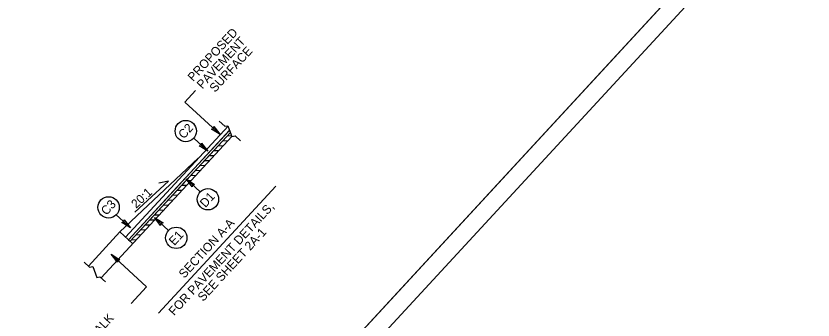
# Model space of a CAD drawing. Extents: x 1768274 to 1769121, y 999922 to 1000687.
# Drawn here: x 1768915.3 to 1769121.4, y 1000054.9 to 1000133.4 of the extents above; entities that cross this region are included whole.
import ezdxf

# ---------------------------------------------------------------- set-up
doc = ezdxf.new("R2010")
doc.units = 0
for name, color, linetype in [('E_NCDOT_Terrain_Model_Contour_Imported', 7, 'Continuous'), ('E_NCDOT_Terrain_Model_Contour_Major', 7, 'Continuous'), ('E_NCDOT_Terrain_Model_Contour_Minor', 7, 'Continuous'), ('E_NCDOT_Terrain_Model_Spot_Elevation', 7, 'Continuous'), ('E_NCDOT_Terrain_Model_Triangles', 7, 'Continuous')]:
    doc.layers.add(name, color=color, linetype=linetype)

msp = doc.modelspace()

# ---------------------------------------------------------------- linework, layer by layer
at = {"layer": 'E_NCDOT_Terrain_Model_Contour_Imported'}
msp.add_lwpolyline([(1768737.29, 1000073.61), (1768947.71, 1000301.25), (1769102.65, 1000158.03), (1768892.23, 999930.38)], close=True, dxfattribs=at)
at = {"layer": 'E_NCDOT_Terrain_Model_Contour_Major'}
msp.add_line((1768892.23, 999930.38), (1769116.23, 1000172.72), dxfattribs=at)
at = {"layer": 'E_NCDOT_Terrain_Model_Contour_Minor'}
msp.add_lwpolyline([(1768944.76, 1000075.2), (1768957.91, 1000089.43), (1768970.71, 1000103.28), (1768970.49, 1000103.9), (1768970.28, 1000103.68), (1768956.94, 1000089.24), (1768944.33, 1000075.6)], close=True, dxfattribs=at)
at = {"layer": 'E_NCDOT_Terrain_Model_Spot_Elevation'}
msp.add_lwpolyline([(1768729.03, 1000071.31), (1768959.82, 1000320.98), (1769121.37, 1000171.65), (1768890.59, 999921.97)], close=True, dxfattribs=at)
at = {"layer": 'E_NCDOT_Terrain_Model_Triangles'}
for p, q in [((1768958.95, 1000111.17), (1768961.7, 1000114.15)), ((1768968.06, 1000102.74), (1768958.95, 1000111.17)), ((1768967.83, 1000106.2), (1768969.24, 1000104.89)), ((1768970.11, 1000104.96), (1768943.6, 1000076.28)), ((1768970.49, 1000103.9), (1768944.33, 1000075.6)), ((1768969.24, 1000104.89), (1768970.08, 1000105.06)), ((1768970.08, 1000105.06), (1768971.08, 1000102.25)), ((1768971.07, 1000102.27), (1768937.31, 1000065.74)), ((1768970.71, 1000103.28), (1768944.76, 1000075.2)), ((1768964.87, 1000098.44), (1768961.22, 1000101.81)), ((1768971.03, 1000102.4), (1768969.86, 1000102.35)), ((1768971.08, 1000102.25), (1768971.92, 1000102.41)), ((1768971.92, 1000102.41), (1768973.33, 1000101.11)), ((1768968.84, 1000099.85), (1768967.5, 1000099.8)), ((1768970.02, 1000101.13), (1768968.68, 1000101.08)), ((1768967.66, 1000098.57), (1768966.32, 1000098.52)), ((1768962.41, 1000096.64), (1768942.16, 1000077.61)), ((1768965.3, 1000096.02), (1768963.96, 1000095.97)), ((1768966.48, 1000097.3), (1768965.14, 1000097.24)), ((1768962.93, 1000093.46), (1768961.6, 1000093.41)), ((1768964.12, 1000094.74), (1768962.78, 1000094.69)), ((1768959.23, 1000091.33), (1768962.87, 1000087.96)), ((1768961.75, 1000092.19), (1768960.42, 1000092.13)), ((1768954.72, 1000090.77), (1768946.02, 1000082.74)), ((1768952.13, 1000056.63), (1768982.44, 1000089.42)), ((1768954.72, 1000090.77), (1768952.18, 1000090.19)), ((1768959.39, 1000089.63), (1768958.05, 1000089.58)), ((1768960.57, 1000090.91), (1768959.24, 1000090.86)), ((1768958.21, 1000088.35), (1768956.87, 1000088.3)), ((1768955.85, 1000085.8), (1768954.51, 1000085.75)), ((1768957.03, 1000087.08), (1768955.69, 1000087.02)), ((1768953.49, 1000083.25), (1768952.15, 1000083.19)), ((1768954.67, 1000084.52), (1768953.33, 1000084.47)), ((1768944.84, 1000078.68), (1768941.2, 1000082.04)), ((1768952.31, 1000081.97), (1768950.97, 1000081.92)), ((1768951.08, 1000081.38), (1768954.72, 1000078.01)), ((1768949.95, 1000079.41), (1768948.61, 1000079.36)), ((1768951.13, 1000080.69), (1768949.79, 1000080.64)), ((1768942.16, 1000077.61), (1768934.01, 1000068.79)), ((1768942.16, 1000077.61), (1768945.46, 1000074.56)), ((1768947.58, 1000076.86), (1768946.25, 1000076.81)), ((1768948.77, 1000078.14), (1768947.43, 1000078.08)), ((1768946.4, 1000075.58), (1768945.07, 1000075.53)), ((1768939.89, 1000071.88), (1768949.01, 1000063.46)), ((1768932.87, 1000069.83), (1768934.28, 1000068.53)), ((1768934.28, 1000068.53), (1768935.12, 1000068.7)), ((1768935.12, 1000068.7), (1768936.13, 1000065.89)), ((1768936.13, 1000065.89), (1768936.97, 1000066.05)), ((1768936.97, 1000066.05), (1768938.37, 1000064.75)), ((1768945.01, 1000059.14), (1768949.01, 1000063.46))]:
    msp.add_line(p, q, dxfattribs=at)
for points in [[(1768966.46, 1000104.83), (1768968.06, 1000102.74), (1768965.84, 1000104.17), (1768966.39, 1000104.29)], [(1768963.27, 1000100.52), (1768964.87, 1000098.44), (1768962.65, 1000099.87), (1768963.2, 1000099.98)], [(1768960.83, 1000089.25), (1768959.23, 1000091.33), (1768961.45, 1000089.9), (1768960.9, 1000089.79)], [(1768952.67, 1000079.3), (1768951.08, 1000081.38), (1768953.3, 1000079.96), (1768952.74, 1000079.84)], [(1768943.24, 1000080.76), (1768944.84, 1000078.68), (1768942.62, 1000080.1), (1768943.17, 1000080.22)], [(1768941.49, 1000069.8), (1768939.89, 1000071.88), (1768942.11, 1000070.45), (1768941.56, 1000070.34)]]:
    msp.add_lwpolyline(points, close=True, dxfattribs=at)
for centre in [(1768959.18, 1000103.66), (1768964.89, 1000086.07), (1768939.2, 1000083.95), (1768956.71, 1000076.1)]:
    msp.add_circle(centre, 2.76, dxfattribs=at)

# ---------------------------------------------------------------- texts
for s, height, rotation, p in [('PROPOSED', 2.274, 47.2512, (1768961.09, 1000116.31)), ('PAVEMENT', 2.274, 47.2512, (1768963.44, 1000114.4)), ('SURFACE', 2.274, 47.2512, (1768966.73, 1000113.5)), ('C2', 2.274, 47.2512, (1768958.65, 1000101.48)), ('20:1', 2.274, 42.7134, (1768946.34, 1000083.57)), ('D1', 2.274, 47.2512, (1768964.24, 1000083.76)), ('C3', 2.274, 47.2512, (1768938.66, 1000081.76)), ('FOR PAVEMENT DETAILS,', 2.2736, 47.2512, (1768956.15, 1000055.86)), ('SECTION A-A', 2.2736, 47.2512, (1768958.78, 1000065.5)), ('E1', 2.274, 47.2512, (1768956.22, 1000073.95)), ('SEE SHEET 2A-1', 2.2736, 47.2512, (1768963.67, 1000059.53)), ('PROPOSED SIDEWALK', 2.2736, 47.2512, (1768917.81, 1000030.44))]:
    msp.add_text(s, height=height, rotation=rotation, dxfattribs=at).set_placement(p)

doc.saveas('drawing.dxf')
